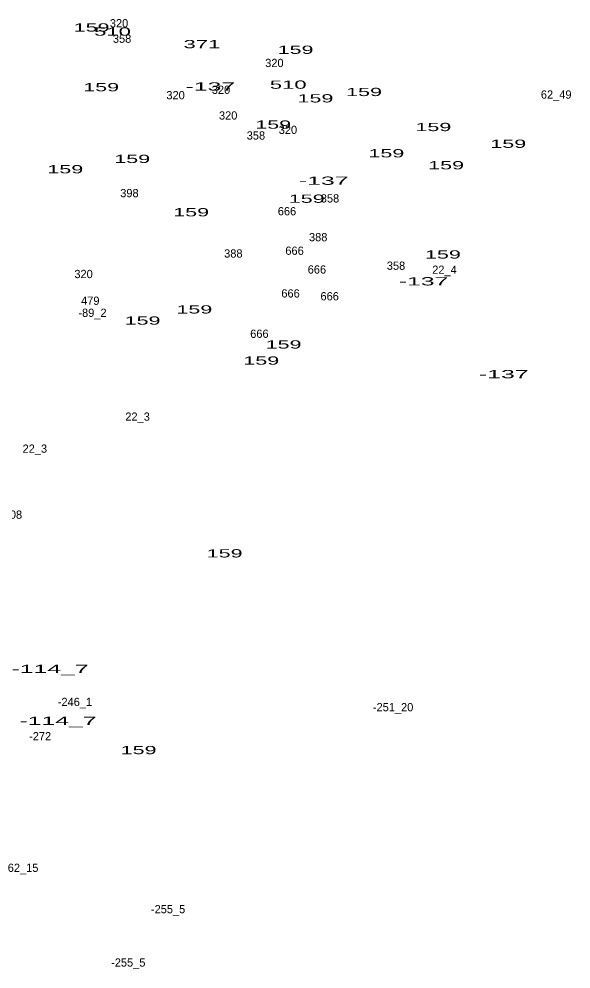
# Model space of a CAD drawing. Extents: x -661742 to -657295, y -1002932 to -996888.
# Drawn here: x -659540.4 to -659272.4, y -1000300.8 to -999839.3 of the extents above; entities that cross this region are included whole.
import ezdxf
from ezdxf.enums import TextEntityAlignment as Align

# ---------------------------------------------------------------- set-up
doc = ezdxf.new("R2010")
doc.units = 0
doc.header["$LTSCALE"] = 1.6
doc.layers.add('24', color=7, linetype='Continuous')

msp = doc.modelspace()

# ---------------------------------------------------------------- texts
at = {"layer": '24'}
for s, width, p in [('159', 1.95, (-659505.183, -999845.44)), ('510', 2, (-659495.024, -999847.43)), ('371', 2, (-659451.613, -999853.55)), ('159', 1.95, (-659406.163, -999856.27)), ('159', 1.95, (-659500.533, -999874.46)), ('-137', 2.25, (-659447.535, -999874.12)), ('510', 2, (-659409.724, -999873.22)), ('159', 1.95, (-659372.893, -999876.78)), ('159', 1.95, (-659396.493, -999879.87)), ('159', 1.95, (-659416.993, -999892.64)), ('159', 1.95, (-659339.243, -999893.8)), ('159', 1.95, (-659302.883, -999901.93)), ('159', 1.95, (-659362.063, -999906.57)), ('159', 1.95, (-659485.453, -999909.28)), ('159', 1.95, (-659517.943, -999914.31)), ('159', 1.95, (-659333.053, -999912.38)), ('-137', 2.25, (-659392.475, -999919.89)), ('159', 1.95, (-659400.743, -999928.63)), ('159', 1.95, (-659456.833, -999935.21)), ('159', 1.95, (-659334.603, -999955.72)), ('-137', 2.25, (-659344.015, -999968.76)), ('159', 1.95, (-659455.283, -999982.41)), ('159', 1.95, (-659480.423, -999987.83)), ('159', 1.95, (-659411.963, -999999.44)), ('159', 1.95, (-659422.793, -1000007.27)), ('-137', 2.25, (-659305.045, -1000013.87)), ('159', 1.95, (-659440.583, -1000100.91)), ('-114_7', 2.25, (-659525.358, -1000157.05)), ('-114_7', 2.25, (-659521.478, -1000182.27)), ('159', 1.95, (-659482.353, -1000196.48))]:
    msp.add_text(s, height=4, dxfattribs=dict(at, width=width)).set_placement(p, align=Align.CENTER)
for s, p in [('320', (-659491.861, -999843.4)), ('358', (-659490.377, -999850.9)), ('320', (-659416.431, -999862.69)), ('320', (-659464.401, -999878.35)), ('320', (-659442.351, -999875.71)), ('62_49', (-659279.61, -999878.03)), ('320', (-659438.871, -999888.21)), ('320', (-659409.861, -999895.18)), ('358', (-659425.397, -999897.92)), ('398', (-659486.813, -999925.91)), ('358', (-659389.427, -999928.48)), ('666', (-659410.313, -999934.71)), ('388', (-659395.157, -999947.31)), ('388', (-659436.357, -999955.24)), ('666', (-659406.633, -999953.9)), ('358', (-659357.377, -999961.18)), ('320', (-659509.071, -999965.21)), ('666', (-659395.783, -999963.02)), ('22_4', (-659333.84, -999963.13)), ('666', (-659408.583, -999974.65)), ('666', (-659389.583, -999976.02)), ('479', (-659505.813, -999978.19)), ('-89_2', (-659504.748, -999984.06)), ('666', (-659423.703, -999994.24)), ('22_3', (-659482.855, -1000034.49)), ('22_3', (-659532.735, -1000050.05)), ('208', (-659543.381, -1000082.11)), ('-246_1', (-659513.266, -1000173.1)), ('-251_20', (-659358.789, -1000175.64)), ('-272', (-659530.161, -1000189.75)), ('62_15', (-659538.444, -1000253.68)), ('-255_5', (-659468.032, -1000273.75)), ('-255_5', (-659487.372, -1000299.68))]:
    msp.add_text(s, height=4, dxfattribs=at).set_placement(p, align=Align.CENTER)

doc.saveas('drawing.dxf')
